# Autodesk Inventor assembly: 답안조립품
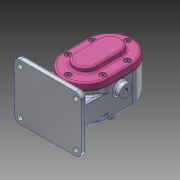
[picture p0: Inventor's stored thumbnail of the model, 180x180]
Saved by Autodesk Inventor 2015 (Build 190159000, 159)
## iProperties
Created: 2020-09
Part Number: 답안조립품
Document SubType Name: Assembly
Designer: Administrator
Author: Administrator
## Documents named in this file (11)
- C:\Users\Administrator.SC-201902071408\Desktop\700906V1048\답안조립품.iam
- C:\Users\Administrator.SC-201902071408\Desktop\700906V1048\본체.ipt
- C:\Users\Administrator.SC-201902071408\Desktop\700906V1048\메인축.ipt
- C:\Users\Administrator.SC-201902071408\Desktop\700906V1048\키 6 x 6 x 18.ipt
- C:\Users\Administrator.SC-201902071408\Desktop\700906V1048\스퍼기어.ipt
- C:\Users\Administrator.SC-201902071408\Desktop\700906V1048\베어링부시.ipt
- C:\Users\Administrator.SC-201902071408\Desktop\700906V1048\서브축.ipt
- C:\Users\Administrator.SC-201902071408\Desktop\700906V1048\개스킷.ipt
- C:\Users\Administrator.SC-201902071408\Desktop\700906V1048\커버.ipt
- C:\Users\Administrator.SC-201902071408\Desktop\700906V1048\오일 실 16 28 7.ipt
- C:\Users\Administrator.SC-201902071408\Desktop\700906V1048\볼트 M5.ipt
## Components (1 placed, 1 different names)
1. 개스킷:1
